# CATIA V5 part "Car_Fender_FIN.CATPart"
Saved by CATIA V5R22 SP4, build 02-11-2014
Part number: Car_Fender
Material "ｱﾙﾐﾆｳﾑ": density 2710 kg/m3, Young's modulus 7e+10 Pa, Poisson ratio 0.346, thermal expansion 2.36e-05 1/K
Bounding box of the stored display mesh (mm): x -800 to 0, y -40 to 122.298, z 0 to 580
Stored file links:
  C:\DATA\Car_ASSY\教育モデル\3_SOL\Car_Fender_FIN.CATPart
  C:\_V5\B22\win_b64\startup\materials\red_env_512x512.jpg
  C:\_V5\B22\win_b64\startup\materials\yellow_env_512x512.jpg
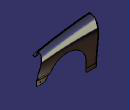
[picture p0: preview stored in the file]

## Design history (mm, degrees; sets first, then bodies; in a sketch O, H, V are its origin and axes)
Set1
  Plane1: type Offset, RefPlane yz-plane, Offset 400, reversed
  Plane2 "平面.2": type Offset, RefPlane Plane1, Offset 400, reversed
Body1 (main body)
  Body2
    Sketch1 on yz-plane, origin (0, 0, 0), H (0, 1, 0), V (0, 0, 1)
      point P1 (40.1932, 0)
      point P2 (100, 50)
      line L1 (100, 50) -> (100, 0)
      point P3 (100, 0)
      line L2 (100, 0) -> (0, 0)
      line L3 (0, 0) -> (0, 450)
      line L4 (0, 450) -> (10, 450)
      point P5 (10, 450)
      spline S1 through (10, 450) (100, 50)
      point P6 (10, 450)
      point P7 (100, 50)
      length L3 = 450
      length L2 = 100
      length L1 = 50
      length L4 = 10
      coincidence: P3 H, P6 P5, P7 P2
      vertical: L1 V, L3 V
      horizontal: L2 H, L4 H
    Sketch2 on Plane1, origin (-400, 0, 0), H (0, 1, 0), V (0, 0, 1)
      point P1 (40.1932, 0)
      point P2 (100, 50)
      line L1 (100, 50) -> (100, 0)
      point P3 (100, 0)
      line L2 (100, 0) -> (0, 0)
      line L3 (0, 0) -> (0, 530)
      line L4 (0, 530) -> (10, 530)
      point P5 (10, 530)
      spline S1 through (10, 530) (100, 50)
      point P6 (10, 530)
      point P7 (100, 50)
      length L3 = 530
      length L2 = 100
      length L1 = 50
      length L4 = 10
      coincidence: P3 H, P6 P5, P7 P2
      vertical: L1 V, L3 V
      horizontal: L2 H, L4 H
    Sketch3 on Plane2, origin (-800, 0, 0), H (0, 1, 0), V (0, 0, 1)
      point P1 (40.1932, 0)
      point P2 (100, 50)
      line L1 (100, 50) -> (100, 0)
      point P3 (100, 0)
      line L2 (100, 0) -> (0, 0)
      line L3 (0, 0) -> (0, 580)
      line L4 (0, 580) -> (10, 580)
      point P5 (10, 580)
      spline S1 through (10, 580) (100, 50)
      point P6 (10, 580)
      point P7 (100, 50)
      length L3 = 580
      length L2 = 100
      length L1 = 50
      length L4 = 10
      coincidence: P3 H, P6 P5, P7 P2
      vertical: L1 V, L3 V
      horizontal: L2 H, L4 H
    Loft1: solid, Sections (Sketch1; Sketch2; Sketch3)
    Body3
      Sketch4 on zx-plane, origin (0, 0, 0), H (-1, 0, 0), V (0, 0, 1)
        line L1 (-46.4952, 240) -> (159.0779, 240)
        arc A1 centre (390, 110) radius 265 from (159.0779, 240) to (655, 109.9999) cw
        point P2 (390, 110)
        line L2 (655, 109.9999) -> (655, -30)
        line L3 (-37.8358, 626.6258) -> (859.9489, 626.6258)
        line L4 (859.9489, 626.6258) -> (850, -30)
        line L5 (850, -30) -> (655, -30)
        line L6 (-37.8358, 626.6258) -> (-46.4952, 240)
        radius A1 = 265
        distance P2 H = 110
        distance V P2 = 390
        distance H L1 = 240
        horizontal: L1 H, L3 H, L5 H
        tangency: L2 A1
        vertical: L2 V
      Pad1: profile Sketch4, direction (0, 1, 0), length 340, mirrored extent
    Intersect1: tool Body3
    Sketch5 on Plane2, origin (-800, 0, 0), H (0, 1, 0), V (0, 0, 1)
      line L1 (0, 580) -> (0, 545)
      line L2 (-5, 540) -> (-40, 540)
      point P2 (-40, 540)
      reference projected line E1 (10, 580) -> (0, 580) from edge [face of Loft1 | face of Loft1]
      reference intersected line E2 (0, 0) -> (0, 580) from face of Loft1
      arc A1 centre (-5, 545) radius 5 from (-5, 540) to (0, 545) ccw
      line L3 (-5, 537) -> (-40, 537)
      arc A2 centre (-5, 545) radius 8 from (-5, 537) to (3, 545) ccw
      line L4 (3, 580) -> (3, 545)
      line L5 (-40, 537) -> (-40, 540)
      line L6 (3, 580) -> (0, 580)
      reference projected line E3 (10, 580) -> (0, 580) from edge [face of Loft1 | face of Loft1]
      distance E1 L2 = 40
      radius A1 = 5
      distance L1 P2 = 40
      length L5 = 3
      length L6 = 3
      radius A2 = 8
      vertical: L1 V, L4 V, L5 V
      horizontal: L2 H, L6 H, L3 H
      coincidence: L1 E2, L6 E3
      tangency: A1 L2, A1 L1, L4 A2, A2 L3
    Shell1: ExtOffset 0, Face (face of Loft1; face of Loft1; face of Pad1 from Sketch4.A1; face of Loft1; face of Pad1 from Sketch4.L1; face of Loft1), IntOffset 3
    Rib1: profile Sketch5, centre curve edge [face of Loft1 | face of Loft1]
    Sketch6 on Plane2, origin (-800, 0, 0), H (0, 1, 0), V (0, 0, 1)
      projected line E1 (97, 0) -> (97, 50) from edge [face of Shell1 | face of Rib1]
      projected curve E2 from edge [face of Shell1 | face of Rib1]
      projected line E3 (10, 576.9862) -> (3, 576.9862) from edge [face of Shell1 | face of Rib1]
      point P6 (3, 576.9862)
      projected line E4 (3, 576.9862) -> (3, 545) from edge [face of Rib1 | face of Rib1]
      projected line E5 (3, 576.9862) -> (3, 399.233) from edge [face of Rib1 | face of Rib1]
      point P7 (3, 576.9862)
      line L1 (97, 0) -> (37, 0)
      line L2 (37, 0) -> (17.9077, 155.4943)
      arc A1 centre (2003, 399.233) radius 2000 from (17.9077, 155.4943) to (3, 399.233) cw
      angle L1 L2 = 97
      length L1 = 60
      radius A1 = 2000
      horizontal: L1 H
      coincidence: P6 P7
      tangency: A1 L2, A1 E4
    Pad2: profile Sketch6, direction (1, 0, 0), length 10, opposite side length -7
    Sketch7 on yz-plane, origin (0, 0, 0), H (0, 1, 0), V (0, 0, 1)
      projected curve E1 from edge [face of Loft1 | face of Shell1]
      projected curve E2 from edge [face of Loft1 | face of Shell1]
      line L1 (103.8705, 240) -> (92.1161, 240)
      line L2 (89.1161, 237) -> (89.1161, 160)
      line L3 (89.1161, 160) -> (86.1161, 160)
      line L4 (86.1161, 160) -> (86.1161, 237)
      line L5 (92.1161, 243) -> (100.927, 243)
      offset curve E3 from edge [face of Loft1 | face of Shell1]
      offset curve E4 from edge [face of Loft1 | face of Shell1]
      line L6 (101.1109, 260) -> (104.111, 260)
      reference projected line E5 (0, 240) -> (106.8716, 240) from edge [face of Pad1 from Sketch4.L1 | face of Loft1]
      arc A1 centre (92.1161, 237) radius 3 from (89.1161, 237) to (92.1161, 240) cw
      arc A2 centre (92.1161, 237) radius 6 from (86.1161, 237) to (92.1161, 243) cw
      length L3 = 3
      distance L5 L1 = 3
      distance E5 L3 = 80
      distance L2 E1 = 15
      radius A1 = 3
      radius A2 = 6
      distance L6 L1 = 20
      horizontal: L1 H, L3 H, L5 H, L6 H
      vertical: L2 V, L4 V
      tangency: A1 L2, A1 L1, A2 L4, A2 L5
    Rib2: profile Sketch7, centre curve edge [face of Pad1 from Sketch4.L1 | face of Shell1]
    Body4
      Sketch8 on zx-plane, origin (0, 0, 0), H (-1, 0, 0), V (0, 0, 1)
        point P1 (0, 300)
        line L1 (0, 300) -> (127.0171, 520)
        line L2 (127.0171, 520) -> (-100, 520)
        line L3 (-100, 520) -> (-100, 300)
        line L4 (-100, 300) -> (0, 300)
        angle L1 L4 = 120
        distance L4 H = 300
        coincidence: P1 V
        horizontal: L2 H, L4 H
        vertical: L3 V
      Pad3: profile Sketch8, direction (0, 1, 0), length 218, mirrored extent
    Remove1: tool Body4
    Sketch9 on xy-plane, origin (0, 0, 0), H (1, 0, 0), V (0, 1, 0)
      line L1 (-730, -50) -> (-730, -25)
      arc A1 centre (-725, -25) radius 5 from (-730, -25) to (-720, -25) cw
      point P3 (-725, -25)
      line L2 (-720, -25) -> (-720, -50)
      line L3 (-720, -50) -> (-730, -50)
      reference projected line E1 (-800, -40) -> (-800, -5) from edge [face of Rib1 | face of Rib1]
      reference projected line E2 (-5.7993, -40) -> (-800, -40) from edge [face of Rib1 | face of Rib1]
      distance E1 L1 = 70
      length L3 = 10
      distance P3 E2 = 15
      radius A1 = 5
      vertical: L1 V
      tangency: A1 L1, L2 A1
      horizontal: L3 H
    Pocket1: profile Sketch9, direction (0, 0, 1), length 657
    RectPattern1: of Pocket1, direction 1 instances 3, spacing 270, along X axis
    Sketch10 on {plane type Tangent, Support face of Rib2, RefPoint {point type OnSurface, Support face of Rib2, RefPoint {point stored without definition}, Length 0, Direction (0, 0, -1000)}}, origin (-34.1531, 89.7232, 188.2636), H (0.9999, -0.0168, 0), V (0, 0, 1)
      point P1 (-15.8415, 1.7364)
      reference projected line E1 (-124.8302, -28.2636) -> (34.1585, -28.2636) from edge [face of Rib2 | face of Rib2]
      reference projected line E2 (34.1585, -28.2636) -> (34.1585, 48.7364) from edge [face of Rib2 | face of Rib2]
      distance P1 E1 = 30
      distance P1 E2 = 50
    Hole1: placed by Sketch10, at (-49.9925, 89.9835, 190) direction (-0.016, -0.9999, 0), diameter 15, through (limit type 3)
    Chamfer1: length 70, angle 35, on edge [face of Rib2 | face of Rib2]
    Fillet1: radius 10, on edge [face of Rib1 | face of Rib1]; edge [face of Rib1 | face of Pad3 from Sketch8.L1]
    Fillet2: radius 5, on edge [face of Rib2 | face of Rib2]; edge [face of Chamfer1 | face of Rib2]; edge [face of Rib2 | face of Chamfer1]
    Fillet3: radius 10, on edge [face of Pad1 from Sketch4.L2 | face of Pad2]
  Add1: tool Body2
